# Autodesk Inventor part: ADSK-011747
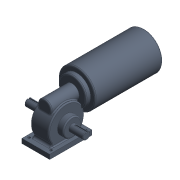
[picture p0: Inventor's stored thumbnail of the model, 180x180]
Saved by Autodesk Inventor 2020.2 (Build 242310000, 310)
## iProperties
Created: 2000-02
Part Number: ADSK-011747
Material: Plomb
Document SubType Name: Modeling
Description: GEARMOTOR,0.25HP,90VDC,68 RPM
Designer: sspink
Density: 11.37 g/cm^3
Appearance: Métal - Plomb
Mass: 24493.4 g
Surface Area: 1296.88 cm^2
Volume: 2154.22 cm^3
Control State: 0
Checked Out: False
Master: False
Shininess: 10.0
Length Units: 11269
Angle Units: 11279
Time Units: 11290
Mass Units: 11283
Length Display Precision: 3
Angle Display Precision: 2
Compacted: True
Cutlength: 23.25
Material Desc: Material Description goes here
Material_Number: Pearson
Dimensions: 144x297,1x160 mm
Mass: 24,493 kg
VLT_Material: Lead
Density: 11.37
Volumn: 1505.3184715831806
Area: 754.7914608636326
PropertySet Name: Model Information
Author: sspink
Revision Number: -
Title: GEARMOTOR,0.25HP,90VDC,68 RPM
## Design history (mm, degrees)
node "Extrusion1" dims "d1" = 185, "d2" = 0
  sketch "Sketch1"
    geometry: C1 r 51 at (0, 0); 1 further point
    constraints: 1 centre point, 1 coincident
    dimensions: "d0" = 102 diameter of C1
node "Extrusion2" dims "d6" = 50, "d7" = 0
  sketch "Sketch2"
    geometry: L1 (-51, 0)-(51, 0) reference; L2 (-51, 185)-(51, 185) reference; L3 (0, 0)-(0, -53); L4 (0, -53)-(45, -53); C1 r 49 at (45, -53)
    constraints: 4 end point, 2 perpendicular, 1 centre point, 1 coincident, 1 midpoint
    dimensions: "d3" = 53 distance of L3.start L3.end; "d4" = 45 distance of L3.end L4.end; "d5" = 98 diameter of C1
node "Extrusion3" dims "d9" = 12.5, "d10" = 0
  sketch "Sketch3"
    geometry: C1 r 51 at (0, 0) reference; C2 r 38.1 at (0, 0)
    constraints: 1 centre point, 1 coincident
    dimensions: "d8" = 76.2 diameter of C2
node "Extrusion4" dims "d12" = 76, "d13" = 0
  sketch "Sketch4"
    geometry: C1 r 19 at (0, 0); A1 r 38.1 centre (0, 0) between (-25, 28.751) and (25, 28.751) reference
    constraints: 1 centre point, 1 coincident
    dimensions: "d11" = 38 diameter of C1
workaxis "Work Axis1"
workplane "Work Plane1"
workplane "Work Plane2"
node "Extrusion5" dims "d21" = 116.0018, "d22" = 0
  sketch "Sketch5"
    geometry: L1 (71.4, 0)-(-71.4, 0) reference; L2 (-38, 48)-(38, 48); L3 (38, 48)-(38, 35.5); L4 (38, 35.5)-(-38, 35.5); L5 (-38, 35.5)-(-38, 48); L6 (0, -125)-(0, 78) reference; 1 further point
    constraints: 8 end point, 2 parallel, 1 horizontal, 1 perpendicular
    dimensions: "d16" = 48 distance between parallel lines of L2 L1; "d17" = 76 distance between parallel lines of L3 L5; "d18" = 38 distance between parallel lines of L6 L5; "d20" = 12.5 distance between parallel lines of L4 L2
node "Extrusion6" dims "d23" = 116.0018, "d24" = 0
node "Hole1" dims "d33" = 6.6, "d34" = 9.525, "d35" = 6.35, "d36" = 60 deg, "d37" = 19.05, "d38" = 118 deg, "d55" = 6
  sketch "Sketch7"
    geometry: L1 (-33.4, -59.144)-(109.4, -59.144) reference; L2 (38, 59.429)-(38, -356.573) reference; 4 further points
    dimensions: "d25" = 30 distance from line of L2 point (8, -11.519); "d26" = 30 distance from line of point (68, -11.519) L2 (= d25); "d27" = 30 distance from line of point (8, -106.644) L2 (= d25); "d28" = 30 distance from line of point (68, -106.644) L2 (= d25); "d29" = 47.625 distance from line of point (8, -11.519) L1; "d30" = 47.625 distance from line of point (68, -11.519) L1; "d31" = 47.5 distance from line of point (8, -106.644) L1 (= d32); "d32" = 47.5 distance from line of point (68, -106.644) L1
node "Extrusion7" dims "d40" = 82.5, "d41" = 0
  sketch "Sketch8"
    geometry: C1 r 25 at (45, -53); 1 further point
    constraints: 1 centre point, 1 coincident
    dimensions: "d39" = 50 diameter of C1
node "Extrusion8" dims "d43" = 160, "d44" = 0
  sketch "Sketch10"
    geometry: C1 r 10 at (45, -53); 1 further point
    constraints: 1 centre point, 1 coincident
    dimensions: "d42" = 20 diameter of C1
node "Extrusion9" dims "d48" = 31.75, "d49" = 0
  sketch "Sketch11"
    geometry: L1 (-2.5, -9.682)-(-2.5, -7); L2 (-2.5, -7)-(2.5, -7); L3 (2.5, -7)-(2.5, -9.682); L4 (0, 76.8)-(0, -124.8) reference; A1 r 10 centre (0, 0) between (-2.5, -9.682) and (2.5, -9.682) reference
    constraints: 6 end point, 2 point on circle, 1 parallel, 1 perpendicular, 1 vertical
    dimensions: "d45" = 5 distance between parallel lines of L3 L1; "d46" = 2.5 distance between parallel lines of L4 L1 (= 0.5 x d45); "d47" = 7 distance from line of L2 A1.centre
fillet "Rundung6"
node "Mirror1"
chamfer "Fase1" distance "d56" = 1; stored, may be unused: second distance "d57" = 2, angle "d58" = 45 deg
node "Fillet1" dims "d50" = 6
node "Fillet2" dims "d51" = 3
node "Fillet4" dims "d53" = 3
node "Fillet5" dims "d54" = 3
fillet "Rundung7" dims "d59" = 3
fillet "Rundung8" dims "d60" = 3
workaxis "Arbeitsachse2"
workplane "Arbeitsebene4"
  workplane "Arbeitsebene3"
workplane "Arbeitsebene5"
node "Solide1"
node "Corps solides"
node "Corps surfaciques"
sketch "Sketch6"
  geometry: L1 (0, 12.5)-(116.002, 12.5) reference; A1 r 49 centre (59.144, -35.5) between (68.993, 12.5) and (49.295, 12.5) reference
other parameters: "d14" = 0, "d15" = 59.1439, "d61" = 0, "d62" = 90 deg
